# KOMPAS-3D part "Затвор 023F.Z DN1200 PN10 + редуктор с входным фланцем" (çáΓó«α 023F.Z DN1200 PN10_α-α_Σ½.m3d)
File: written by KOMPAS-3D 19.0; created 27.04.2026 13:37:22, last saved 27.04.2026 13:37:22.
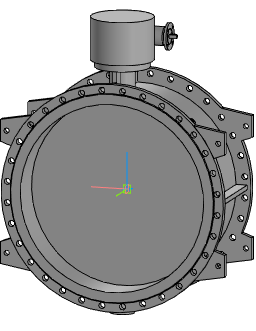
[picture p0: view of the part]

Document properties: Полное имя файла: ..\..\Затвор 023F.Z DN200-DN1600_редуктор с входным фланцем\Затвор 023F.Z DN1200 PN10 + редуктор с входным фланцем.a3d

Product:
- Part/product: Затвор 023F.Z DN1200 PN10 + редуктор с входным фланцем
    Масса: 2053.95

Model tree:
1. Операция без истории:1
